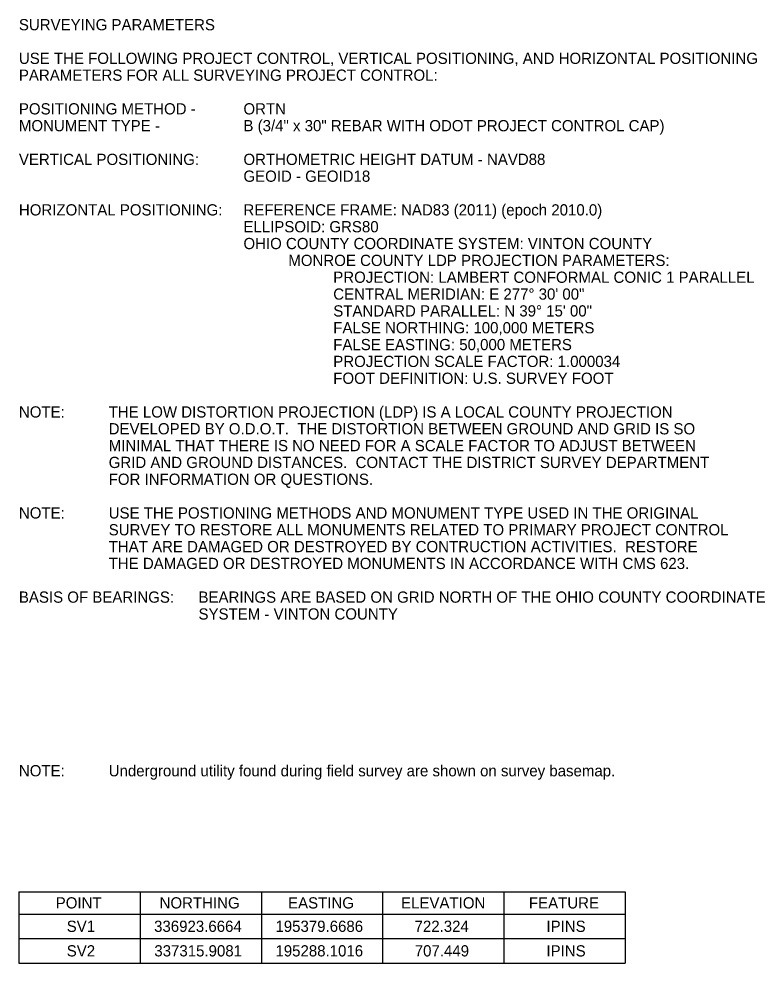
# Model space of a CAD drawing. Extents: x 2030588 to 2035216, y 462285 to 465007.
# Drawn here: x 2030588.2 to 2030774.3, y 464016.8 to 464252.4 of the extents above; entities that cross this region are included whole.
import ezdxf

# ---------------------------------------------------------------- set-up
doc = ezdxf.new("R2010")
doc.units = 0
doc.layers.add('SV_X_Text', color=7, linetype='Continuous')

msp = doc.modelspace()

# ---------------------------------------------------------------- linework, layer by layer
at = {"layer": 'SV_X_Text'}
for p, q in [((2030588.25, 464034.65), (2030739.43, 464034.65)), ((2030588.25, 464034.65), (2030588.25, 464029.08)), ((2030618.48, 464034.65), (2030618.48, 464029.08)), ((2030648.72, 464034.65), (2030648.72, 464029.08)), ((2030678.96, 464034.65), (2030678.96, 464029.08)), ((2030709.19, 464034.65), (2030709.19, 464029.08)), ((2030739.43, 464034.65), (2030739.43, 464029.08)), ((2030588.25, 464029.08), (2030739.43, 464029.08)), ((2030588.25, 464029.08), (2030739.43, 464029.08)), ((2030588.25, 464029.08), (2030588.25, 464016.83)), ((2030618.48, 464029.08), (2030618.48, 464016.83)), ((2030648.72, 464029.08), (2030648.72, 464016.83)), ((2030678.96, 464029.08), (2030678.96, 464016.83)), ((2030709.19, 464029.08), (2030709.19, 464016.83)), ((2030739.43, 464029.08), (2030739.43, 464016.83)), ((2030588.25, 464022.96), (2030739.43, 464022.96)), ((2030588.25, 464016.83), (2030739.43, 464016.83))]:
    msp.add_line(p, q, dxfattribs=at)

# ---------------------------------------------------------------- texts
for s, height, p in [('SURVEYING PARAMETERS', 2.7997, (2030588.25, 464249.51)), ('USE THE FOLLOWING PROJECT CONTROL, VERTICAL POSITIONING, AND HORIZONTAL POSITIONING ', 2.7997, (2030588.25, 464241.12)), ('PARAMETERS FOR ALL SURVEYING PROJECT CONTROL:', 2.7997, (2030588.25, 464236.92)), ('POSITIONING METHOD - ', 2.7997, (2030588.25, 464228.52)), ('ORTN', 2.8, (2030644.24, 464228.52)), ('MONUMENT TYPE - ', 2.7997, (2030588.25, 464224.32)), ('B (3/4" x 30" REBAR WITH ODOT PROJECT CONTROL CAP)', 2.7997, (2030644.24, 464224.32)), ('VERTICAL POSITIONING:', 2.7997, (2030588.25, 464215.92)), ('ORTHOMETRIC HEIGHT DATUM - NAVD88', 2.7997, (2030644.24, 464215.92)), ('GEOID - GEOID18 ', 2.7997, (2030644.24, 464211.72)), ('HORIZONTAL POSITIONING:', 2.7997, (2030588.25, 464203.32)), ('REFERENCE FRAME: NAD83 (2011) (epoch 2010.0)', 2.7997, (2030644.24, 464203.32)), ('ELLIPSOID: GRS80', 2.7997, (2030644.24, 464199.12)), ('OHIO COUNTY COORDINATE SYSTEM: VINTON COUNTY', 2.7997, (2030644.24, 464194.92)), ('MONROE COUNTY LDP PROJECTION PARAMETERS:', 2.7997, (2030655.44, 464190.72)), ('PROJECTION: LAMBERT CONFORMAL CONIC 1 PARALLEL', 2.7997, (2030666.64, 464186.52)), ('CENTRAL MERIDIAN: E 277%%D 30\' 00"', 2.7997, (2030666.64, 464182.32)), ('STANDARD PARALLEL: N 39%%D 15\' 00"', 2.7997, (2030666.64, 464178.12)), ('FALSE NORTHING: 100,000 METERS', 2.7997, (2030666.64, 464173.92)), ('FALSE EASTING: 50,000 METERS', 2.7997, (2030666.64, 464169.72)), ('PROJECTION SCALE FACTOR: 1.000034', 2.7997, (2030666.64, 464165.52)), ('FOOT DEFINITION: U.S. SURVEY FOOT', 2.7997, (2030666.64, 464161.32)), ('NOTE:', 2.8, (2030588.25, 464152.92)), ('THE LOW DISTORTION PROJECTION (LDP) IS A LOCAL COUNTY PROJECTION', 2.7997, (2030610.64, 464152.92)), ('DEVELOPED BY O.D.O.T.  THE DISTORTION BETWEEN GROUND AND GRID IS SO', 2.7997, (2030610.64, 464148.72)), ('MINIMAL THAT THERE IS NO NEED FOR A SCALE FACTOR TO ADJUST BETWEEN', 2.7997, (2030610.64, 464144.52)), ('GRID AND GROUND DISTANCES.  CONTACT THE DISTRICT SURVEY DEPARTMENT', 2.7997, (2030610.64, 464140.32)), ('FOR INFORMATION OR QUESTIONS.', 2.7997, (2030610.64, 464136.13)), ('NOTE:', 2.8, (2030588.25, 464127.73)), ('USE THE POSTIONING METHODS AND MONUMENT TYPE USED IN THE ORIGINAL ', 2.7997, (2030610.64, 464127.73)), ('SURVEY TO RESTORE ALL MONUMENTS RELATED TO PRIMARY PROJECT CONTROL', 2.7997, (2030610.64, 464123.53)), ('THAT ARE DAMAGED OR DESTROYED BY CONTRUCTION ACTIVITIES.  RESTORE ', 2.7997, (2030610.64, 464119.33)), ('THE DAMAGED OR DESTROYED MONUMENTS IN ACCORDANCE WITH CMS 623.', 2.7997, (2030610.64, 464115.13)), ('BASIS OF BEARINGS:', 2.7997, (2030588.25, 464106.73)), ('BEARINGS ARE BASED ON GRID NORTH OF THE OHIO COUNTY COORDINATE', 2.7997, (2030633.04, 464106.73)), ('SYSTEM - VINTON COUNTY', 2.7997, (2030633.04, 464102.53)), ('NOTE:', 2.8, (2030588.25, 464063.42)), ('Underground utility found during field survey are shown on survey basemap.', 2.7997, (2030610.64, 464063.42)), ('POINT', 2.8, (2030597.43, 464030.46)), ('NORTHING', 2.8, (2030623.33, 464030.46)), ('EASTING', 2.8, (2030655.37, 464030.46)), ('ELEVATION', 2.8, (2030683.55, 464030.46)), ('FEATURE', 2.8, (2030715.43, 464030.46)), ('SV1', 2.8, (2030600.17, 464024.62)), ('336923.6664', 2.7997, (2030621.96, 464024.62)), ('195379.6686', 2.7997, (2030652.22, 464024.62)), ('722.324', 2.8, (2030686.91, 464024.62)), ('IPINS', 2.8, (2030719.8, 464024.62)), ('SV2', 2.8, (2030600.18, 464018.5)), ('337315.9081', 2.7997, (2030622.02, 464018.5)), ('195288.1016', 2.7997, (2030652.22, 464018.5)), ('707.449', 2.8, (2030686.96, 464018.5)), ('IPINS', 2.8, (2030719.8, 464018.49))]:
    msp.add_text(s, height=height, rotation=359.9993, dxfattribs=at).set_placement(p)

doc.saveas('drawing.dxf')
